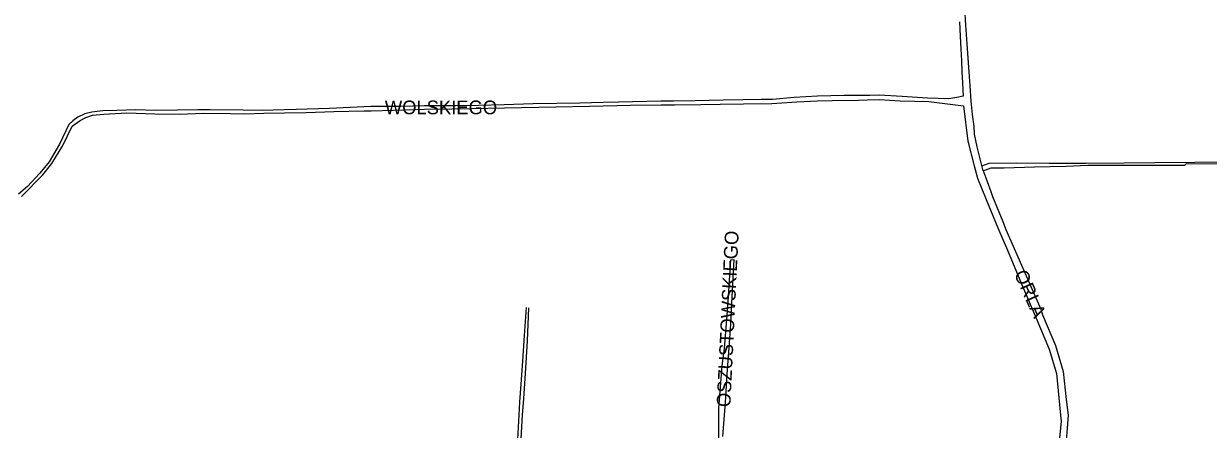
# Model space of a CAD drawing. Extents: x -304109 to -273954, y 21500 to 39796.
# Drawn here: x -302292 to -301430, y 30490 to 30785 of the extents above; entities that cross this region are included whole.
import ezdxf

# ---------------------------------------------------------------- set-up
doc = ezdxf.new("R2010")
doc.units = 0
doc.layers.add('krawedzie_ulic', color=7, linetype='Continuous')
doc.layers.add('nazwy_ulic', color=7, linetype='Continuous')

msp = doc.modelspace()

# ---------------------------------------------------------------- linework, layer by layer
at = {"layer": 'krawedzie_ulic'}
for points in [[(-301593.281, 30677.798), (-301594.467, 30681.691), (-301597.835, 30695.331), (-301599.666, 30704.563), (-301600, 30710.208), (-301601.135, 30718.729), (-301602.174, 30728.624), (-301602.895, 30739.659), (-301603.578, 30750), (-301603.805, 30753.067), (-301605.007, 30770.187), (-301605.902, 30783.803), (-301606.815, 30796.478)], [(-301610.723, 30786.225), (-301610.108, 30775.861), (-301609.705, 30766.739), (-301609.204, 30757.899), (-301608.811, 30750), (-301608.459, 30742.002), (-301607.98, 30732.113), (-301612.587, 30731.195), (-301618.389, 30730.263), (-301633.93, 30730.828), (-301652.361, 30731.906), (-301669.194, 30732.814), (-301675.749, 30732.729), (-301694.473, 30732.589), (-301713.961, 30732.255), (-301730.942, 30731.107), (-301746.629, 30729.869), (-301754.912, 30729.776), (-301768.404, 30729.482), (-301782.735, 30729.171), (-301802.908, 30728.894), (-301818.687, 30728.547), (-301827.985, 30728.464), (-301858.755, 30727.863), (-301870.063, 30727.521), (-301887.011, 30727.135), (-301903.679, 30726.797), (-301921.007, 30726.517), (-301941.946, 30725.943), (-301960.723, 30725.499), (-301977.164, 30725.082), (-301984.175, 30725.129), (-302000, 30725.119), (-302017.222, 30724.688), (-302039.003, 30724.766), (-302069.223, 30723.194), (-302093.521, 30722.383), (-302102.111, 30722.181), (-302118.098, 30721.623), (-302131.975, 30721.98), (-302155.892, 30722.134), (-302164.991, 30722.16), (-302179.758, 30722.009), (-302195.821, 30721.858), (-302210.206, 30722.291), (-302223.83, 30721.861), (-302234.403, 30721.404), (-302242.231, 30720.567), (-302247.263, 30719.272), (-302252.244, 30716.833), (-302255.879, 30714.192), (-302258.852, 30711.525), (-302265.713, 30697.275), (-302273.261, 30684.295), (-302280.021, 30676.141), (-302288.967, 30666.439), (-302295.447, 30660.774)], [(-302293.363, 30659.199), (-302277.886, 30674.846), (-302271.304, 30683.126), (-302263.299, 30696.157), (-302256.336, 30710.432), (-302250.719, 30714.547), (-302246.475, 30716.731), (-302241.748, 30718.382), (-302233.36, 30718.991), (-302216.764, 30719.929), (-302209.952, 30719.802), (-302196.202, 30719.216), (-302178.411, 30719.012), (-302160.924, 30719.874), (-302141.15, 30719.466), (-302130.755, 30719.338), (-302117.056, 30719.718), (-302102.01, 30720.047), (-302086.252, 30720.401), (-302072.654, 30720.781), (-302066.02, 30720.907), (-302043.934, 30721.439), (-302038.876, 30721.566), (-302022.686, 30721.996), (-302006.597, 30722.528), (-302000, 30722.68), (-301980.183, 30723.004), (-301965.676, 30723.237), (-301941.715, 30723.781), (-301904.34, 30724.365), (-301880.024, 30724.828), (-301859.95, 30725.385), (-301850.192, 30725.616), (-301827.683, 30725.844), (-301818.08, 30725.898), (-301798.975, 30726.059), (-301784.822, 30726.346), (-301767.875, 30726.656), (-301747.296, 30726.903), (-301729.07, 30727.937), (-301713.895, 30728.875), (-301703.35, 30729.072), (-301684.143, 30729.308), (-301677.714, 30729.471), (-301668.77, 30729.685), (-301653.689, 30728.87), (-301632.942, 30728.201), (-301607.699, 30725.047), (-301604.515, 30699.453), (-301600, 30681.419), (-301597.541, 30672.495), (-301591.184, 30656.847), (-301582.625, 30636.366), (-301575.754, 30620.062), (-301565.407, 30595.429), (-301554.83, 30570.646), (-301545.389, 30547.885), (-301540.006, 30530.35), (-301536.981, 30500), (-301536.586, 30495.496), (-301538.99, 30470.703)], [(-301594.414, 30681.518), (-301588.915, 30683.312), (-301569.297, 30683.525), (-301545.28, 30683.393), (-301518.29, 30683.412), (-301490.692, 30683.615), (-301468.381, 30683.875), (-301439.437, 30684.165), (-301416.21, 30684.357)], [(-301422.905, 30682.701), (-301445.525, 30682.819), (-301446.735, 30681.666), (-301467.728, 30681.721), (-301481.222, 30681.686), (-301502.748, 30681.661), (-301517.182, 30681.592), (-301532.96, 30681.056), (-301556.108, 30680.585), (-301578.11, 30679.845), (-301587.741, 30679.714), (-301591.644, 30678.412), (-301593.281, 30677.798)], [(-301593.281, 30677.798), (-301593.108, 30677.231), (-301587.726, 30662.744), (-301586.552, 30659.07), (-301579.055, 30640.917), (-301576.845, 30635.067), (-301567.231, 30612.968), (-301560.392, 30597.401), (-301551.376, 30577), (-301550.173, 30572.92), (-301540.735, 30550.54), (-301535.265, 30531.659), (-301532.909, 30511.304), (-301531.466, 30500), (-301533.722, 30471.631)], [(-301785.855, 30478.667), (-301785.895, 30500), (-301785.843, 30505.098), (-301784.564, 30520.356), (-301783.384, 30535.818), (-301781.6, 30548.402), (-301779.221, 30578.716), (-301777.155, 30613.098), (-301774.918, 30613.253), (-301776.324, 30586.029), (-301777.399, 30566.069), (-301778.493, 30549.056), (-301779.842, 30529.658), (-301781.012, 30512.671), (-301781.959, 30500), (-301783.212, 30484.476)], [(-301926.007, 30578.206), (-301927.467, 30557.793), (-301928.656, 30539.13), (-301929.898, 30522.576), (-301930.849, 30509.5), (-301931.457, 30500), (-301935.412, 30425.675), (-301982.139, 30431.824), (-301984.389, 30434.331), (-301986.509, 30446.831)], [(-301930.226, 30474.312), (-301928.738, 30500), (-301927.774, 30512.035), (-301926.566, 30530.19), (-301925.146, 30553.932), (-301924.053, 30577.958)]]:
    msp.add_lwpolyline(points, dxfattribs=at)

# ---------------------------------------------------------------- texts
at = {"layer": 'nazwy_ulic'}
msp.add_text('WOLSKIEGO', height=10, dxfattribs=at).set_placement((-302028.862, 30719.006))
for s, rotation, p in [('OSZUSTOWSKIEGO', 87.250744, (-301777.439, 30505.584)), ('ORLA', 293.950158, (-301571.095, 30603.002))]:
    msp.add_text(s, height=10, rotation=rotation, dxfattribs=at).set_placement(p)

doc.saveas('drawing.dxf')
